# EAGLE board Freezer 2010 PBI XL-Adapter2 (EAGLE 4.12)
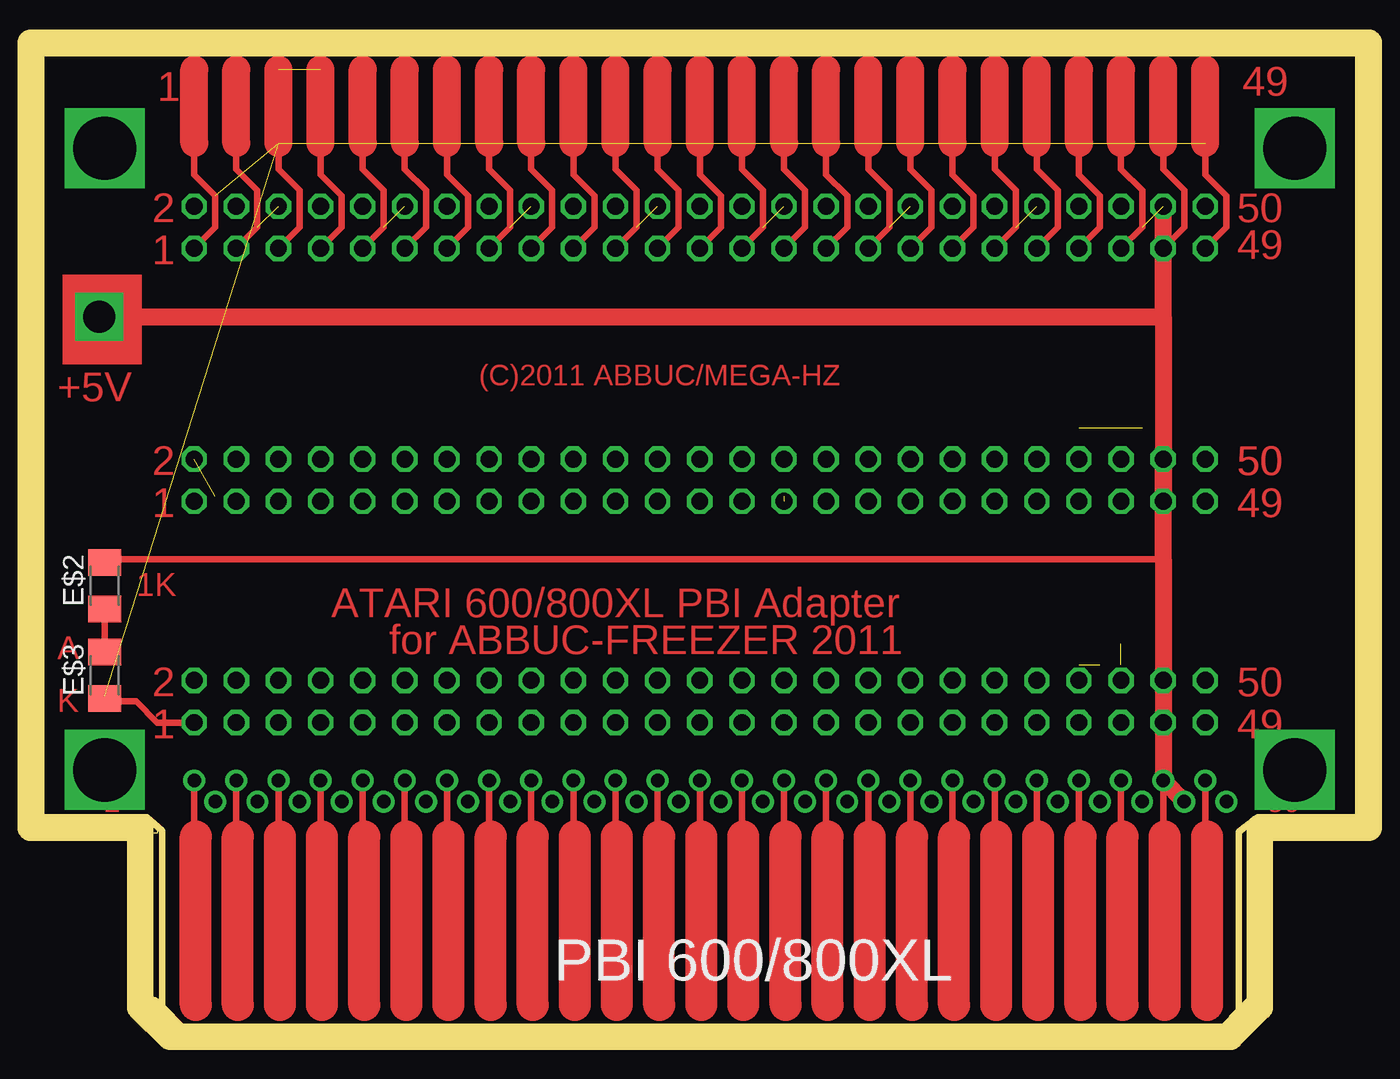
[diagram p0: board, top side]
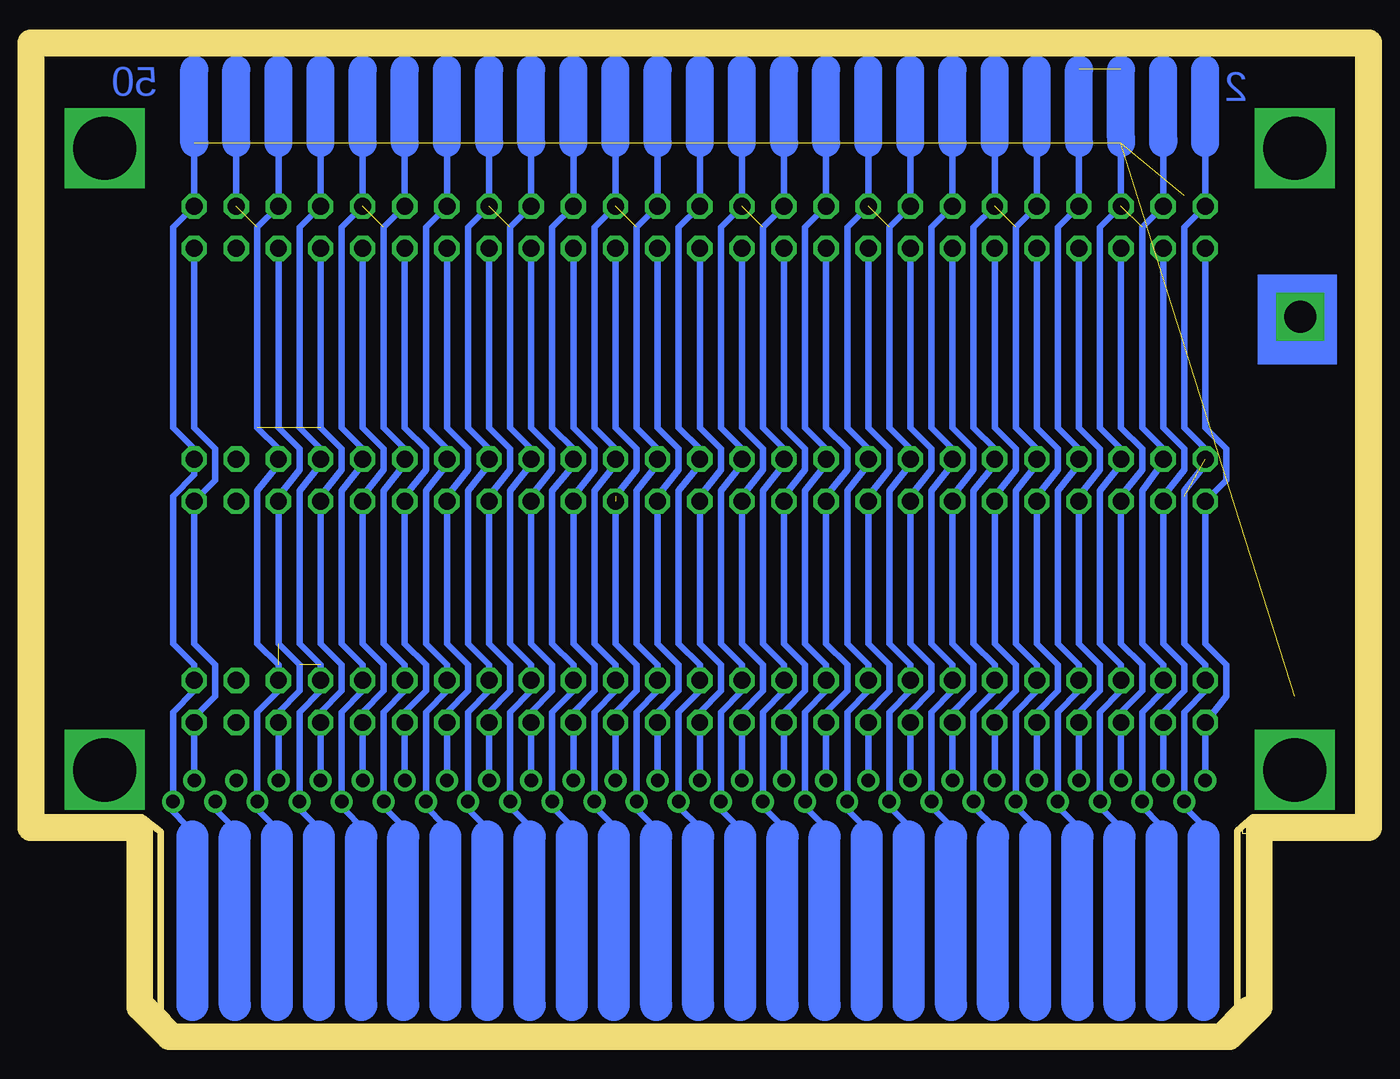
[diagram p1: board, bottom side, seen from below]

Size 79.38 x 58.74 mm. Coordinates in mm from the lower left corner, seen from the top.
Outline: 0,58.74 79.38,58.74 79.38,12.7 73.34,12.7 72.17,11.83 72.17,0.95 71.12,0 8.57,0 7.27,1.3 7.27,11.88 6.35,12.7 0,12.7 0,58.74
Copper layers (1*16): Top 0.035mm / dielectric 1.5mm / Bottom 0.035mm
Design rules "ITead_rule": minimum track width 6mil, minimum drill 12mil, track to track 6mil, track to pad 6mil, pad to pad 6mil, via to via 6mil, smd to smd 0mil, copper to edge 10mil, drill to drill 10mil, minimum pad ring 10mil, minimum via ring 6mil, stop-mask expansion 2mil, vias tented up to drill 100mil, thermal gap 10mil
Net classes: 2 3.3: width 0.508 mm, drill 0.254 mm
Milling: 5 lines

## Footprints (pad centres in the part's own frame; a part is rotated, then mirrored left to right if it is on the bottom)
M1206 = smd 1.6 x 2: 1 -1.4,0; 2 1.4,0
XL-PBI = drill 0.813 round: A0 31.115,-8.255; A1 29.845,-6.985; A2 28.575,-8.255; A3 27.305,-6.985; A4 26.035,-8.255; A5 24.765,-6.985; A6 23.495,-8.255; A7 20.955,-8.255; A8 19.685,-6.985; A9 18.415,-8.255; A10 17.145,-6.985; A11 15.875,-8.255; A12 14.605,-6.985; A13 13.335,-8.255; A14 12.065,-6.985; A15 9.525,-6.985; AUDIO -27.305,-8.255; CAS -17.145,-8.255; D0 8.255,-8.255; D1 6.985,-6.985; D2 5.715,-8.255; D3 4.445,-6.985; D4 3.175,-8.255; D5 1.905,-6.985; D6 0.635,-8.255; D7 -0.635,-6.985; EXT.B -13.335,-6.985; EXTSEL 32.385,-6.985; GND -28.575,-6.985; GND2 -18.415,-6.985; GND3 -5.715,-6.985; GND4 -3.175,-6.985; GND5 22.225,-6.985; GND6 33.655,-8.255; GND7 10.795,-8.255; GND8 -1.905,-8.255; GND9 -22.225,-8.255; IRQ -9.525,-8.255; MPD -19.685,-8.255; NC2 -6.985,-8.255; NC3 -12.065,-8.255; NC4 -14.605,-8.255; PHI2 -4.445,-8.255; RAS -20.955,-6.985; RDY -10.795,-6.985; REF -15.875,-6.985; RST -8.255,-6.985; RW -23.495,-6.985; VCC -24.765,-8.255; VCC1 -26.035,-6.985

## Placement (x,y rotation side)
E$2  [M1206]  3.81,26.67 90 top
E$3  [M1206]  3.81,21.27 90 top
U$3  XL-PBI  [XL-PBI]  42.86,6.67 180 top

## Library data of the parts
E$2 E$3 = rcl
U$3 = wf-atari

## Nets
N$1: U$3.EXTSEL
N$16: U$3.AUDIO
N$28: U$3.VCC U$3.VCC1
N$32: U$3.GND9
N$33: U$3.MPD
N$34: U$3.CAS
N$35: U$3.NC4
N$37: U$3.NC3
N$38: U$3.IRQ
N$48: U$3.NC2
N$81: U$3.PHI2
N$88: U$3.GND8
N$89: U$3.D6
N$90: U$3.D4
N$91: U$3.D2
N$92: U$3.D0
N$93: U$3.GND7
N$94: U$3.A13
N$95: U$3.A11
N$96: U$3.A9
N$97: U$3.A7
N$98: U$3.A6
N$99: U$3.A4
N$102: U$3.RW
N$103: U$3.RAS
N$104: U$3.GND2
N$105: U$3.REF
N$106: U$3.EXT.B
N$107: U$3.RDY
N$108: U$3.RST
N$109: U$3.GND3
N$110: U$3.GND4
N$111: U$3.D7
N$112: U$3.D5
N$113: U$3.D3
N$114: U$3.D1
N$115: U$3.A15
N$116: U$3.A14
N$117: U$3.A12
N$118: U$3.A10
N$119: U$3.A8
N$120: U$3.GND5
N$122: U$3.A5
N$126: U$3.A1 U$3.A3
N$159: U$3.GND6
N$190: U$3.GND
N$307: U$3.A2
N$354: U$3.A0

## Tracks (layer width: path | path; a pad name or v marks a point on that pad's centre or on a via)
N$1  (via drill 1.02)  (1 unrouted)
  Bottom 0.406: 9.21,56.2 9.21,49.53 10.48,48.26 10.48,36.2 9.21,34.92 v9.21,34.29 | 10.48,32.07 10.48,23.18 9.21,21.91 v9.21,20.95 9.21,20.32 10.48,19.05 U$3.EXTSEL
N$16  (via drill 1.02)
  Bottom 0.406: U$3.AUDIO v70.17,18.41 70.17,18.73 68.9,20 68.9,21.91 70.17,23.18 70.17,31.75 68.9,33.02 68.9,34.92 70.17,36.2 v70.17,46.99
N$23  (via drill 1.02)
  other vias: 70.17,49.53
N$28  (via drill 1.02)
  Top 0.406: 3.81,27.62 arc-90 4.13,28.26 67.63,28.26
  Top 1.016: 67.63,31.12 67.63,28.26 v67.63,20.95 v67.63,18.41 U$3.VCC U$3.VCC1
N$29  (via drill 1.02, 1.93)
  Top 0.406: 67.63,53.02 67.63,51.75 68.9,50.48 68.9,48.26 67.63,46.99
  Top 1.016: v67.63,31.75 v67.63,34.29 67.63,42.86 | 4.13,42.86 3.18,42.86 | 4.13,42.86 67.63,42.86 | v3.49,42.86 4.13,42.86 | 67.63,42.86 67.63,46.99 v67.63,49.53
N$30  (via drill 1.02)
  other vias: 65.09,49.53
N$31  (via drill 1.02)
  other vias: 62.55,49.53
N$32  (via drill 1.02)
  Bottom 0.406: U$3.GND9 v65.09,18.41
N$33  (via drill 1.02)
  Bottom 0.406: U$3.MPD v62.55,18.41
N$34  (via drill 1.02)
  Bottom 0.406: U$3.CAS v60.01,18.41
N$35  (via drill 1.02)
  Bottom 0.406: U$3.NC4 v57.47,18.41
N$36  (via drill 1.02)
  other vias: 60.01,49.53
N$37  (via drill 1.02)
  Bottom 0.406: U$3.NC3 v54.93,18.41
N$38  (via drill 1.02)
  Bottom 0.406: U$3.IRQ v52.39,18.41
N$39  (via drill 1.02)
  other vias: 57.47,49.53
N$40  (via drill 1.02)
  other vias: 54.93,49.53
N$41  (via drill 1.02)
  other vias: 52.39,49.53
N$42  (via drill 1.02)
  other vias: 49.85,49.53
N$43  (via drill 1.02)
  other vias: 47.31,49.53
N$44  (via drill 1.02)
  other vias: 44.77,49.53
N$45  (via drill 1.02)
  other vias: 42.23,49.53
N$46  (via drill 1.02)
  other vias: 39.69,49.53
N$47  (via drill 1.02)
  other vias: 37.15,49.53
N$48  (via drill 1.02)
  Bottom 0.406: U$3.NC2 v49.85,18.41
N$49  (via drill 1.02)
  other vias: 34.61,49.53
N$50  (via drill 1.02)
  other vias: 32.07,49.53
N$51  (via drill 1.02)
  other vias: 29.53,49.53
N$52  (via drill 1.02)
  other vias: 26.99,49.53
N$53  (via drill 1.02)
  other vias: 24.45,49.53
N$54  (via drill 1.02)
  other vias: 21.91,49.53
N$55  (via drill 1.02)
  other vias: 19.37,49.53
N$56  (via drill 1.02)
  other vias: 16.83,49.53
N$58
  Top 0.406: 19.37,53.34 19.37,51.75 20.64,50.48 20.64,48.26 19.37,46.99
N$59
  Top 0.406: 16.83,46.99 18.1,48.26 18.1,50.16 16.83,51.44 16.83,53.34
N$60
  Top 0.406: 21.91,53.02 21.91,51.75 23.18,50.48 23.18,48.26 21.91,46.99
N$62
  Top 0.406: 26.99,53.34 26.99,51.75 28.26,50.48 28.26,48.26 26.99,46.99
N$63
  Top 0.406: 24.45,46.99 25.72,48.26 25.72,50.16 24.45,51.44 24.45,53.34
N$64
  Top 0.406: 29.53,53.02 29.53,51.75 30.8,50.48 30.8,48.26 29.53,46.99
N$66
  Top 0.406: 34.61,53.34 34.61,51.75 35.88,50.48 35.88,48.26 34.61,46.99
N$67
  Top 0.406: 32.07,46.99 33.34,48.26 33.34,50.16 32.07,51.44 32.07,53.34
N$68
  Top 0.406: 37.15,53.02 37.15,51.75 38.42,50.48 38.42,48.26 37.15,46.99
N$70
  Top 0.406: 42.23,53.34 42.23,51.75 43.5,50.48 43.5,48.26 42.23,46.99
N$71
  Top 0.406: 39.69,46.99 40.96,48.26 40.96,50.16 39.69,51.44 39.69,53.34
N$72
  Top 0.406: 44.77,53.02 44.77,51.75 46.04,50.48 46.04,48.26 44.77,46.99
N$74
  Top 0.406: 49.85,53.34 49.85,51.75 51.12,50.48 51.12,48.26 49.85,46.99
N$75
  Top 0.406: 47.31,46.99 48.58,48.26 48.58,50.16 47.31,51.44 47.31,53.34
N$76
  Top 0.406: 52.39,53.02 52.39,51.75 53.66,50.48 53.66,48.26 52.39,46.99
N$78
  Top 0.406: 57.47,53.34 57.47,51.75 58.74,50.48 58.74,48.26 57.47,46.99
N$80
  Top 0.406: 54.93,46.99 56.2,48.26 56.2,50.16 54.93,51.44 54.93,53.34
N$81  (via drill 1.02)
  Bottom 0.406: U$3.PHI2 v47.31,18.41
N$82
  Top 0.406: 60.01,53.02 60.01,51.75 61.28,50.48 61.28,48.26 60.01,46.99
N$84
  Top 0.406: 65.09,53.34 65.09,51.75 66.36,50.48 66.36,48.26 65.09,46.99
N$85
  Top 0.406: 62.55,46.99 63.82,48.26 63.82,50.16 62.55,51.44 62.55,53.34
N$87
  Top 0.406: 70.17,46.99 71.44,48.26 71.44,50.16 70.17,51.44 70.17,53.34
N$88  (via drill 1.02)
  Bottom 0.406: U$3.GND8 v44.77,18.41
N$89  (via drill 1.02)
  Bottom 0.406: U$3.D6 v42.23,18.41
N$90  (via drill 1.02)
  Bottom 0.406: U$3.D4 v39.69,18.41
N$91  (via drill 1.02)
  Bottom 0.406: U$3.D2 v37.15,18.41
N$92  (via drill 1.02)
  Bottom 0.406: U$3.D0 v34.61,18.41
N$93  (via drill 1.02)
  Bottom 0.406: U$3.GND7 v32.07,18.41
N$94  (via drill 1.02)
  Bottom 0.406: U$3.A13 v29.53,18.41
N$95  (via drill 1.02)
  Bottom 0.406: U$3.A11 v26.99,18.41
N$96  (via drill 1.02)
  Bottom 0.406: U$3.A9 v24.45,18.41
N$97  (via drill 1.02)
  Bottom 0.406: U$3.A7 v21.91,18.41
N$98  (via drill 1.02)
  Bottom 0.406: U$3.A6 v19.37,18.41
N$99  (via drill 1.02)
  Bottom 0.406: U$3.A4 v16.83,18.41 16.83,19.05 15.56,20.32 15.56,21.91 16.83,23.18 16.83,32.07 15.56,33.66 15.56,34.92 16.83,36.2 v16.83,46.99
N$102
  Bottom 0.406: U$3.RW 66.36,19.05
N$103
  Bottom 0.406: U$3.RAS 63.82,19.05
N$104
  Bottom 0.406: U$3.GND2 61.28,19.05
N$105
  Bottom 0.406: U$3.REF 58.74,19.05
N$106
  Bottom 0.406: U$3.EXT.B 56.2,19.05
N$107
  Bottom 0.406: U$3.RDY 53.66,19.05
N$108
  Bottom 0.406: U$3.RST 51.12,19.05
N$109
  Bottom 0.406: U$3.GND3 48.58,19.05
N$110
  Bottom 0.406: U$3.GND4 46.04,19.05
N$111
  Bottom 0.406: U$3.D7 43.5,19.05
N$112
  Bottom 0.406: U$3.D5 40.96,19.05
N$113
  Bottom 0.406: U$3.D3 38.42,19.05
N$114
  Bottom 0.406: U$3.D1 35.88,19.05
N$115
  Bottom 0.406: U$3.A15 33.34,19.05
N$116
  Bottom 0.406: U$3.A14 30.8,19.05
N$117
  Bottom 0.406: U$3.A12 28.26,19.05
N$118
  Bottom 0.406: U$3.A10 25.72,19.05
N$119
  Bottom 0.406: U$3.A8 23.18,19.05
N$120
  Bottom 0.406: U$3.GND5 20.64,19.05
N$122
  Bottom 0.406: U$3.A5 18.1,19.05
N$123
  Bottom 0.406: 18.1,13.65 18.1,19.05 16.83,20.32 16.83,21.91 18.1,23.18
N$125
  Bottom 0.406: 20.64,13.65 20.64,19.05 19.37,20.32 19.37,21.91 20.64,23.18
N$126  (via drill 1.02)  (23 unrouted)
  Bottom 0.406: U$3.A1 13.02,19.05 11.75,20.32 v11.75,20.95 11.75,21.91 13.02,23.18 13.02,32.38 11.73,34.14 11.75,34.92 13.02,36.2 13.02,48.26 v11.75,49.53 11.75,53.66 | 14.29,53.66 v14.29,49.53 15.56,48.26 15.56,36.2 14.29,34.92 14.29,33.97 15.56,32.38 15.56,23.18 14.29,21.91 v14.29,20.95 14.29,20.32 15.56,19.05 U$3.A3
  Bottom 1.676: 70.17,53.34 70.17,57.78 | 67.63,53.34 67.63,57.78 | 65.09,53.34 65.09,57.78 | 62.55,53.34 62.55,57.78 | 60.01,53.34 60.01,57.78 | 57.47,53.34 57.47,57.78 | 54.93,53.34 54.93,57.78 | 52.39,53.34 52.39,57.78 | 49.85,53.34 49.85,57.78 | 47.31,53.34 47.31,57.78 | 44.77,53.34 44.77,57.78 | 42.23,53.34 42.23,57.78 | 39.69,53.34 39.69,57.78 | 37.15,53.34 37.15,57.78 | 34.61,53.34 34.61,57.78 | 32.07,53.34 32.07,57.78 | 29.53,53.34 29.53,57.78 | 26.99,53.34 26.99,57.78 | 24.45,53.34 24.45,57.78 | 21.91,53.34 21.91,57.78 | 19.37,53.34 19.37,57.78 | 16.83,53.34 16.83,57.78 | 11.75,53.34 11.75,53.66 11.75,57.78 | 14.29,53.34 14.29,53.66 14.29,57.78
N$129
  Bottom 0.406: 23.18,13.65 23.18,19.05 21.91,20.32 21.91,21.91 23.18,23.18
N$130
  Bottom 0.406: 25.72,13.65 25.72,19.05 24.45,20.32 24.45,21.91 25.72,23.18
N$132  (via drill 1.02)
  Bottom 0.406: 29.53,18.41 29.53,19.05 28.26,20.32 28.26,21.91 29.53,23.18 29.53,32.07 28.26,33.66 28.26,34.92 29.53,36.2 v29.53,46.99
N$133
  Bottom 0.406: 28.26,13.65 28.26,19.05 26.99,20.32 26.99,21.91 28.26,23.18
N$134
  Bottom 0.406: 30.8,13.65 30.8,19.05 29.53,20.32 29.53,21.91 30.8,23.18
N$137
  Bottom 0.406: 33.34,13.65 33.34,19.05 32.07,20.32 32.07,21.91 33.34,23.18
N$138
  Bottom 0.406: 35.88,13.65 35.88,19.05 34.61,20.32 34.61,21.91 35.88,23.18
N$140  (via drill 1.02)
  Bottom 0.406: 39.69,18.41 39.69,19.05 38.42,20.32 38.42,21.91 39.69,23.18 39.69,32.07 38.42,33.66 38.42,34.92 39.69,36.2 v39.69,46.99
N$141
  Bottom 0.406: 38.42,13.65 38.42,19.05 37.15,20.32 37.15,21.91 38.42,23.18
N$142
  Bottom 0.406: 40.96,13.65 40.96,19.05 39.69,20.32 39.69,21.91 40.96,23.18
N$144  (via drill 1.02)  (1 unrouted)
  Bottom 0.406: 44.77,18.41 44.77,19.05 43.5,20.32 43.5,21.91 44.77,23.18 44.77,32.07 43.5,33.66 43.5,34.92 44.77,36.2 v44.77,46.99
  other vias: 44.77,31.75
N$145
  Bottom 0.406: 43.5,13.65 43.5,19.05 42.23,20.32 42.23,21.91 43.5,23.18
N$146
  Bottom 0.406: 46.04,13.65 46.04,19.05 44.77,20.32 44.77,21.91 46.04,23.18
N$148  (via drill 1.02)
  Bottom 0.406: 49.85,18.41 49.85,19.05 48.58,20.32 48.58,21.91 49.85,23.18 49.85,32.07 48.58,33.66 48.58,34.92 49.85,36.2 v49.85,46.99
N$149
  Bottom 0.406: 48.58,13.65 48.58,19.05 47.31,20.32 47.31,21.91 48.58,23.18
N$150
  Bottom 0.406: 51.12,13.65 51.12,19.05 49.85,20.32 49.85,21.91 51.12,23.18
N$152  (via drill 1.02)
  Bottom 0.406: 54.93,18.41 54.93,19.05 53.66,20.32 53.66,21.91 54.93,23.18 54.93,32.07 53.66,33.66 53.66,34.92 54.93,36.2 v54.93,46.99
N$153
  Bottom 0.406: 53.66,13.65 53.66,19.05 52.39,20.32 52.39,21.91 53.66,23.18
N$154
  Bottom 0.406: 56.2,13.65 56.2,19.05 54.93,20.32 54.93,21.91 56.2,23.18
N$156  (via drill 1.02)
  Bottom 0.406: 60.01,18.41 60.01,19.05 58.74,20.32 58.74,21.91 60.01,23.18 60.01,32.07 58.74,33.66 58.74,34.92 60.01,36.2 v60.01,46.99
N$157
  Bottom 0.406: 58.74,13.65 58.74,19.05 57.47,20.32 57.47,21.91 58.74,23.18
N$158
  Bottom 0.406: 61.28,13.65 61.28,19.05 60.01,20.32 60.01,21.91 61.28,23.18
N$159  (via drill 1.02)  (24 unrouted)
  Top 0.406: v9.21,46.99 10.48,48.26 10.48,50.16 9.21,51.44 9.21,53.34 | v9.21,18.41 6.99,18.41 5.72,19.68 3.81,19.68 3.81,20 3.81,20.32
  Top 1.676: 9.21,53.34 9.21,57.78 | 14.29,53.34 14.29,57.78 | 16.83,53.34 16.83,57.78 | 19.37,53.34 19.37,57.78 | 21.91,53.34 21.91,57.78 | 24.45,53.34 24.45,57.78 | 26.99,53.34 26.99,57.78 | 29.53,53.34 29.53,57.78 | 32.07,53.34 32.07,57.78 | 34.61,53.34 34.61,57.78 | 37.15,53.34 37.15,57.78 | 39.69,53.34 39.69,57.78 | 42.23,53.34 42.23,57.78 | 44.77,53.34 44.77,57.78 | 47.31,53.34 47.31,57.78 | 49.85,53.34 49.85,57.78 | 52.39,53.34 52.39,57.78 | 54.93,53.34 54.93,57.78 | 57.47,53.34 57.47,57.78 | 60.01,53.34 60.01,57.78 | 62.55,53.34 62.55,57.78 | 65.09,53.34 65.09,57.78 | 67.63,53.34 67.63,57.78 | 70.17,53.34 70.17,57.78
  Bottom 0.406: 9.21,36.2 9.21,46.67 | 7.94,34.92 7.94,33.34 | 9.21,30.16 9.21,28.89 | 9.21,36.2 v9.21,46.99 | 7.94,34.92 9.21,36.2 | 7.94,34.92 7.94,33.02 v9.21,31.75 9.21,30.16 | 9.21,30.16 9.21,23.18 7.94,21.91 7.94,20 v9.21,18.41 U$3.GND6
N$160
  Bottom 0.406: 11.75,31.43 11.75,32.07 10.48,33.66 10.48,34.92 11.75,36.2 11.75,46.67
N$162
  Top 1.016: 67.63,31.43 67.63,33.97
N$166
  Bottom 0.406: 10.48,47.94 10.48,36.2 9.21,34.92 9.21,33.97 10.48,32.38 10.48,27.62
N$169
  Bottom 0.406: 18.1,23.18 18.1,32.07
N$170
  Bottom 0.406: 20.64,23.18 20.64,32.07
N$171
  Bottom 0.406: 23.18,23.18 23.18,32.07
N$172
  Bottom 0.406: 25.72,23.18 25.72,32.07
N$173
  Bottom 0.406: 28.26,23.18 28.26,32.07
N$174
  Bottom 0.406: 30.8,23.18 30.8,32.07
N$175
  Bottom 0.406: 33.34,23.18 33.34,32.07
N$176
  Bottom 0.406: 35.88,23.18 35.88,32.07
N$177
  Bottom 0.406: 38.42,23.18 38.42,32.07
N$178
  Bottom 0.406: 40.96,23.18 40.96,32.07
N$179
  Bottom 0.406: 43.5,23.18 43.5,32.07
N$180
  Bottom 0.406: 46.04,23.18 46.04,32.07
N$181
  Bottom 0.406: 48.58,23.18 48.58,32.07
N$182  (via drill 1.02)
  other vias: 11.75,34.29
N$183
  Bottom 0.406: 51.12,23.18 51.12,32.07
N$184
  Bottom 0.406: 66.36,23.18 66.36,32.38
N$185
  Bottom 0.406: 63.82,23.18 63.82,32.38
N$186
  Bottom 0.406: 61.28,23.18 61.28,32.07
N$187
  Bottom 0.406: 58.74,23.18 58.74,32.07
N$188
  Bottom 0.406: 56.2,23.18 56.2,32.07
N$189
  Bottom 0.406: 53.66,23.18 53.66,32.07
N$190
  Bottom 0.406: U$3.GND 71.44,19.05 70.17,20.32 70.17,21.91 71.44,23.18 71.44,32.07 70.17,33.34 70.17,34.92 71.44,36.2 71.44,48.26 70.17,49.53 70.17,56.2
N$191  (via drill 1.02)
  Bottom 0.406: 21.91,18.41 21.91,19.05 20.64,20.32 20.64,21.91 21.91,23.18 21.91,32.07 20.64,33.66 20.64,34.92 21.91,36.2 v21.91,46.99
N$193
  Bottom 0.406: 18.1,23.18 18.1,32.38 16.83,33.97 16.83,34.92 18.1,36.2 18.1,48.26 16.83,49.53 16.83,56.2
N$195  (via drill 1.02)
  Bottom 0.406: 26.99,18.41 26.99,19.05 25.72,20.32 25.72,21.91 26.99,23.18 26.99,32.07 25.72,33.66 25.72,34.92 26.99,36.2 v26.99,46.99
N$197  (1 unrouted)
  Bottom 0.406: 23.18,23.18 23.18,32.38 21.91,33.97 21.91,34.92 23.18,36.2 23.18,48.26 21.91,49.53 21.91,53.66 | 20.64,23.18 20.64,32.38 19.37,33.97 19.37,34.92 20.64,36.2 20.64,48.26 19.37,49.53 19.37,53.66
N$198
  Bottom 0.406: 25.72,23.18 25.72,32.38 24.45,33.97 24.45,34.92 25.72,36.2 25.72,48.26 24.45,49.53 24.45,56.2
N$199  (via drill 1.02)
  Bottom 0.406: 32.07,18.41 32.07,19.05 30.8,20.32 30.8,21.91 32.07,23.18 32.07,32.07 30.8,33.66 30.8,34.92 32.07,36.2 v32.07,46.99
N$202  (1 unrouted)
  Bottom 0.406: 30.8,23.18 30.8,32.38 29.53,33.97 29.53,34.92 30.8,36.2 30.8,48.26 29.53,49.53 29.53,53.66 | 28.26,23.18 28.26,32.38 26.99,33.97 26.99,34.92 28.26,36.2 28.26,48.26 26.99,49.53 26.99,53.66
N$203  (via drill 1.02)
  Bottom 0.406: 37.15,18.41 37.15,19.05 35.88,20.32 35.88,21.91 37.15,23.18 37.15,32.07 35.88,33.66 35.88,34.92 37.15,36.2 v37.15,46.99
N$204  (via drill 1.02)
  Bottom 0.406: 34.61,18.41 34.61,19.05 33.34,20.32 33.34,21.91 34.61,23.18 34.61,32.07 33.34,33.66 33.34,34.92 34.61,36.2 v34.61,46.99
N$205
  Bottom 0.406: 33.34,23.18 33.34,32.38 32.07,33.97 32.07,34.92 33.34,36.2 33.34,48.26 32.07,49.53 32.07,56.2
N$207  (via drill 1.02)
  Bottom 0.406: 42.23,18.41 42.23,19.05 40.96,20.32 40.96,21.91 42.23,23.18 42.23,32.07 40.96,33.66 40.96,34.92 42.23,36.2 v42.23,46.99
N$209  (1 unrouted)
  Bottom 0.406: 38.42,23.18 38.42,32.38 37.15,33.97 37.15,34.92 38.42,36.2 38.42,48.26 37.15,49.53 37.15,53.66 | 35.88,23.18 35.88,32.38 34.61,33.97 34.61,34.92 35.88,36.2 35.88,48.26 34.61,49.53 34.61,53.66
N$210
  Bottom 0.406: 40.96,23.18 40.96,32.38 39.69,33.97 39.69,34.92 40.96,36.2 40.96,48.26 39.69,49.53 39.69,56.2
N$211  (via drill 1.02)
  Bottom 0.406: 47.31,18.41 47.31,19.05 46.04,20.32 46.04,21.91 47.31,23.18 47.31,32.07 46.04,33.66 46.04,34.92 47.31,36.2 v47.31,46.99
N$214  (1 unrouted)
  Bottom 0.406: 46.04,23.18 46.04,32.38 44.77,33.97 44.77,34.92 46.04,36.2 46.04,48.26 44.77,49.53 44.77,53.66 | 43.5,23.18 43.5,32.38 42.23,33.97 42.23,34.92 43.5,36.2 43.5,48.26 42.23,49.53 42.23,53.66
N$215  (via drill 1.02)
  Bottom 0.406: 52.39,18.41 52.39,19.05 51.12,20.32 51.12,21.91 52.39,23.18 52.39,32.07 51.12,33.66 51.12,34.92 52.39,36.2 v52.39,46.99
N$217
  Bottom 0.406: 48.58,23.18 48.58,32.38 46.99,34.29 47.31,34.92 48.58,36.2 48.58,48.26 47.31,49.53 47.31,56.2
N$219  (via drill 1.02)
  Bottom 0.406: 57.47,31.75 57.47,31.43 | 57.47,31.75 57.47,32.07 56.2,33.66 56.2,34.92 57.47,36.2 v57.47,46.99 | 57.47,18.41 57.47,19.05 56.2,20.32 56.2,21.91 57.47,23.18 57.47,31.75
N$221  (1 unrouted)
  Bottom 0.406: 53.66,23.18 53.66,32.38 52.39,33.97 52.39,34.92 53.66,36.2 53.66,48.26 52.39,49.53 52.39,53.66 | 51.12,23.18 51.12,32.38 49.85,33.97 49.85,34.92 51.12,36.2 51.12,48.26 49.85,49.53 49.85,53.66
N$222
  Bottom 0.406: 56.2,23.18 56.2,32.38 54.93,33.97 54.93,34.92 56.2,36.2 56.2,48.26 54.93,49.53 54.93,56.2
N$223  (via drill 1.02)  (6 unrouted)
  Bottom 0.406: 63.82,32.38 62.55,33.97 62.55,34.92 63.82,36.2 63.82,48.26 62.55,49.53 62.55,56.2 | 66.36,32.38 65.09,33.97 65.09,34.92 66.36,36.2 66.36,48.26 65.09,49.53 65.09,53.66 | 62.55,18.41 62.55,19.05 61.28,20.32 61.28,21.91 62.55,23.18 62.55,32.07 61.28,33.66 61.28,34.92 62.55,36.2 v62.55,46.99 | 63.82,19.05 62.55,20.32 62.55,21.91 63.82,23.18 | 65.09,19.05 63.82,20.32 63.82,21.91 65.09,23.18 65.09,32.07 63.82,33.66 63.82,34.92 65.09,36.2 v65.09,46.99 | 66.36,19.05 65.09,20.32 65.09,21.91 66.36,23.18 | 67.63,49.53 67.63,53.66
N$226  (1 unrouted)
  Bottom 0.406: 61.28,23.18 61.28,32.38 60.01,33.97 60.01,34.92 61.28,36.2 61.28,48.26 60.01,49.53 60.01,53.66 | 58.74,23.18 58.74,32.38 57.47,33.97 57.47,34.92 58.74,36.2 58.74,48.26 57.47,49.53 57.47,53.66
N$231  (via drill 3.81)
  other vias: 3.81,53.02
N$232  (via drill 3.81)
  other vias: 75.56,53.02
N$233  (via drill 3.81)
  other vias: 75.56,15.56
N$234  (via drill 3.81)
  other vias: 3.81,15.56
N$284  (via drill 1.02)
  other vias: 67.63,46.99
N$301  (via drill 1.02)
  Bottom 0.406: 24.45,18.41 24.45,19.05 23.18,20.32 23.18,21.91 24.45,23.18 24.45,31.75 | 24.45,31.75 24.45,31.43 | 24.45,31.75 24.45,32.07 23.18,33.66 23.18,34.92 24.45,36.2 v24.45,46.99
N$303  (via drill 1.02)
  Bottom 0.406: 19.37,18.41 19.37,19.05 18.1,20.32 18.1,21.91 19.37,23.18 19.37,32.07 18.1,33.66 18.1,34.92 19.37,36.2 v19.37,46.99
N$304  (via drill 1.02)
  Top 0.406: 11.75,53.34 11.75,51.75 13.02,50.48 13.02,48.26 v11.75,46.99
  Top 1.676: 11.75,53.34 11.75,57.78
N$307  (via drill 1.02)
  Top 0.406: 14.29,53.02 14.29,51.75 15.56,50.48 15.56,48.26 v14.29,46.99
  Bottom 0.406: 14.29,46.67 v14.29,46.99 14.29,36.2 13.02,34.92 13.02,33.66 14.29,32.07 14.29,31.75 | U$3.A2 v14.29,18.41 14.29,19.05 13.02,20.32 13.02,21.91 14.29,23.18 14.29,31.75 | 14.29,31.75 14.29,31.43
N$308  (via drill 1.02)
  other vias: 70.17,31.75
N$310  (via drill 1.02)
  other vias: 65.09,31.75
N$311  (via drill 1.02)
  other vias: 62.55,31.75
N$312  (via drill 1.02)
  other vias: 60.01,31.75
N$313  (via drill 1.02)
  other vias: 57.47,31.75
N$314  (via drill 1.02)
  other vias: 54.93,31.75
N$315  (via drill 1.02)
  other vias: 52.39,31.75
N$316  (via drill 1.02)
  other vias: 49.85,31.75
N$317  (via drill 1.02)
  other vias: 47.31,31.75
N$319  (via drill 1.02)
  other vias: 42.23,31.75
N$320  (via drill 1.02)
  other vias: 39.69,31.75
N$321  (via drill 1.02)
  other vias: 37.15,31.75
N$322  (via drill 1.02)
  other vias: 34.61,31.75
N$323  (via drill 1.02)
  other vias: 32.07,31.75
N$324  (via drill 1.02)
  other vias: 29.53,31.75
N$325  (via drill 1.02)
  other vias: 26.99,31.75
N$326  (via drill 1.02)
  other vias: 24.45,31.75
N$327  (via drill 1.02)
  other vias: 21.91,31.75
N$328  (via drill 1.02)
  other vias: 19.37,31.75
N$330  (via drill 1.02)
  other vias: 16.83,31.75
N$332  (via drill 1.02)
  other vias: 14.29,31.75
N$333  (via drill 1.02)
  other vias: 70.17,34.29
N$335  (via drill 1.02)
  other vias: 65.09,34.29
N$336  (via drill 1.02)
  other vias: 62.55,34.29
N$337  (via drill 1.02)
  other vias: 60.01,34.29
N$338  (via drill 1.02)
  other vias: 57.47,34.29
N$339  (via drill 1.02)
  other vias: 54.93,34.29
N$340  (via drill 1.02)
  other vias: 52.39,34.29
N$341  (via drill 1.02)
  other vias: 49.85,34.29
N$342  (via drill 1.02)
  other vias: 47.31,34.29
N$343  (via drill 1.02)
  other vias: 44.77,34.29
N$344  (via drill 1.02)
  other vias: 42.23,34.29
N$345  (via drill 1.02)
  other vias: 39.69,34.29
N$346  (via drill 1.02)
  other vias: 37.15,34.29
N$347  (via drill 1.02)
  other vias: 34.61,34.29
N$348  (via drill 1.02)
  other vias: 32.07,34.29
N$349  (via drill 1.02)
  other vias: 29.53,34.29
N$350  (via drill 1.02)
  other vias: 26.99,34.29
N$351  (via drill 1.02)
  other vias: 24.45,34.29
N$352  (via drill 1.02)
  other vias: 21.91,34.29
N$353  (via drill 1.02)
  other vias: 19.37,34.29
N$354  (via drill 1.02)
  Bottom 0.406: U$3.A0 v11.75,18.41 11.75,19.05 10.48,20.32 10.48,21.91 11.75,23.18 v11.75,31.75
N$355  (via drill 1.02)
  other vias: 16.83,34.29
N$357  (via drill 1.02)
  other vias: 14.29,34.29
S$1
  Top 0.406: 3.81,22.54 3.81,24.45
S$3
  Bottom 1.676: 9.21,53.34 9.21,57.78
S$6  (via drill 1.02)
  other vias: 9.21,49.53
S$8  (via drill 1.02)
  other vias: 16.83,20.95
S$9  (via drill 1.02)
  other vias: 19.37,20.95
S$11  (via drill 1.02)
  other vias: 21.91,20.95
S$13  (via drill 1.02)
  other vias: 24.45,20.95
S$15  (via drill 1.02)
  other vias: 26.99,20.95
S$17  (via drill 1.02)
  other vias: 29.53,20.95
S$19  (via drill 1.02)
  other vias: 32.07,20.95
S$21  (via drill 1.02)
  other vias: 34.61,20.95
S$23  (via drill 1.02)
  other vias: 37.15,20.95
S$24  (via drill 1.02)
  other vias: 39.69,20.95
S$25  (via drill 1.02)
  other vias: 42.23,20.95
S$26  (via drill 1.02)
  other vias: 44.77,20.95
S$27  (via drill 1.02)
  other vias: 47.31,20.95
S$28  (via drill 1.02)
  other vias: 49.85,20.95
S$29  (via drill 1.02)
  other vias: 65.09,20.95
S$30  (via drill 1.02)
  other vias: 62.55,20.95
S$31  (via drill 1.02)
  other vias: 60.01,20.95
S$32  (via drill 1.02)
  other vias: 57.47,20.95
S$33  (via drill 1.02)
  other vias: 54.93,20.95
S$34  (via drill 1.02)
  other vias: 52.39,20.95
S$35  (via drill 1.02)
  other vias: 70.17,20.95
(copper drawn outside any net)
  shapes: Bottom area x1, Top area x1

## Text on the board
Top: 1 | 49 | 2 | 50 | 1 | 49 | (C)2011 ABBUC/MEGA-HZ | +5V | 2 | 50 | 50 | 1 | 49 | 1K | ATARI 600/800XL PBI Adapter | A | for ABBUC-FREEZER 2011 | 2 | 50 | K | 1 | 49
Bottom: 2 | 50
tStop: 2 | 50 | 1 | 49 | (C)2011 ABBUC/MEGA-HZ | +5V | 2 | 50 | 1 | 49 | 1K | ATARI 600/800XL PBI Adapter | A | for ABBUC-FREEZER 2011 | 2 | 50 | K | 1 | 49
